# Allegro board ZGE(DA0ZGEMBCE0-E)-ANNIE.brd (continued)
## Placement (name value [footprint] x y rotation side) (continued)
C541  1u/10V_2  [C0201]  138.37 129.56 180 bottom
C542  1u/10V_2  [C0201]  131.2 129.16 0 bottom
C543  1u/10V_2  [C0201]  132.74 128.92 0 bottom
C544  1u/10V_2  [C0201]  129.74 128.87 180 bottom
C545  1u/10V_2  [C0201]  136.03 128.69 180 bottom
C546  1u/10V_2  [C0201]  139.51 128.64 0 bottom
C547  10u/6.3V_4  [C0402_2]  126.89 128.59 180 bottom
C548  1u/10V_2  [C0201]  143.1 128.51 180 bottom
C549  1u/10V_2  [C0201]  131.18 128.44 0 bottom
C550  1u/10V_2  [C0201]  144.62 128.31 180 bottom
C551  1u/10V_2  [C0201]  138.24 128.19 90 bottom
C552  1u/10V_2  [C0201]  129.74 128.11 180 bottom
C553  1u/10V_2  [C0201]  128.42 128.01 0 bottom
C554  10u/6.3V_4  [C0402_2]  132.54 127.94 0 bottom
C555  1u/10V_2  [C0201]  124.94 127.93 270 bottom
C556  1u/10V_2  [C0201]  143.1 127.78 180 bottom
C557  10u/6.3V_4  [C0402_2]  136.24 127.7 180 bottom
C558  10u/6.3V_4  [C0402_2]  139.67 127.62 0 bottom
C559  22u/6.3V_6  [C0603]  109.62 127.55 180 bottom
C560  1u/10V_2  [C0201]  144.62 127.55 180 bottom
C561  1u/10V_2  [C0201]  128.41 127.27 0 bottom
C562  10u/6.3V_4  [C0402_2]  127.04 127.27 180 bottom
C563  1u/10V_2  [C0201]  134.73 127.17 180 bottom
C564  *10u/6.3V_4  [C0402_2]  129.89 127.06 180 bottom
C565  1u/10V_2  [C0201]  143.1 127.04 180 bottom
C566  1u/10V_2  [C0201]  144.62 126.84 180 bottom
C567  10u/6.3V_4  [C0402_2]  132.28 126.57 0 bottom
C568  10u/6.3V_4  [C0402_2]  139.67 126.43 0 bottom
C569  10u/6.3V_4  [C0402_2]  136.11 126.43 180 bottom
C570  1u/10V_2  [C0201]  138.22 126.41 90 bottom
C571  *1u/10V_2  [C0201]  134.69 126.33 180 bottom
C572  *1u/10V_2  [C0201]  144.65 126.1 180 bottom
C573  10u/6.3V_4  [C0402_2]  143.07 126.07 180 bottom
C574  10u/6.3V_4  [C0402_2]  127.32 125.92 180 bottom
C575  1u/6.3V_4  [C0402]  125.27 125.8 180 bottom
C576  *10u/6.3V_4  [C0402_2]  129.89 125.79 180 bottom
C577  *1u/10V_2  [C0201]  134.69 125.56 180 bottom
C578  10u/6.3V_4  [C0402_2]  132.28 125.38 0 bottom
C579  *1u/10V_2  [C0201]  144.65 125.37 180 bottom
C580  10u/6.3V_4  [C0402_2]  139.67 125.16 0 bottom
C581  10u/6.3V_4  [C0402_2]  136.11 125.16 180 bottom
C582  1u/10V_2  [C0201]  124.63 124.91 180 bottom
C583  10u/6.3V_4  [C0402_2]  143.07 124.88 180 bottom
C584  10u/6.3V_4  [C0402_2]  127.35 124.73 180 bottom
C585  *10u/6.3V_4  [C0402_2]  129.89 124.52 180 bottom
C586  10u/6.3V_4  [C0402_2]  132.31 124.19 0 bottom
C587  10u/6.3V_4  [C0402_2]  139.67 123.89 0 bottom
C588  10u/6.3V_4  [C0402_2]  136.11 123.89 180 bottom
C589  1u/10V_2  [C0201]  123.41 123.89 90 bottom
C590  10u/6.3V_4  [C0402_2]  144.01 123.64 180 bottom
C591  10u/6.3V_4  [C0402_2]  127.42 123.53 180 bottom
C592  *10u/6.3V_4  [C0402_2]  129.89 123.25 180 bottom
C593  10u/6.3V_4  [C0402_2]  132.3 123 0 bottom
C594  22u/6.3V_6  [C0603]  124.99 122.98 90 bottom
C595  10u/6.3V_4  [C0402_2]  139.67 122.62 0 bottom
C596  10u/6.3V_4  [C0402_2]  136.11 122.62 180 bottom
C597  10u/6.3V_4  [C0402_2]  144.01 122.44 180 bottom
C598  10u/6.3V_4  [C0402_2]  127.4 122.32 180 bottom
C599  *10u/6.3V_4  [C0402_2]  129.89 121.98 180 bottom
C600  10u/6.3V_4  [C0402_2]  132.3 121.73 0 bottom
C601  0.1u/10V_2  [C0201]  172.36 121.71 0 bottom
C602  22u/6.3V_6  [C0603]  139.67 121.22 0 bottom
C603  22u/6.3V_6  [C0603]  136.11 121.22 180 bottom
C604  22u/6.3V_6  [C0603]  143.55 121.12 180 bottom
C605  10u/6.3V_4  [C0402_2]  127.78 121.1 180 bottom
C606  0.1u/10V_2  [C0201]  172.36 120.95 0 bottom
C607  10u/6.3V_4  [C0402_2]  129.89 120.71 180 bottom
C608  10u/6.3V_4  [C0402_2]  124.57 120.47 0 bottom
C609  10u/6.3V_4  [C0402_2]  132.3 120.46 0 bottom
C610  0.1u/10V_2  [C0201]  172.36 120.18 0 bottom
C611  22u/6.3V_6  [C0603]  127.37 119.75 180 bottom
C612  22u/6.3V_6  [C0603]  143.55 119.7 180 bottom
C613  22u/6.3V_6  [C0603]  139.67 119.7 0 bottom
C614  22u/6.3V_6  [C0603]  136.11 119.7 180 bottom
C615  10u/6.3V_4  [C0402_2]  129.89 119.44 180 bottom
C616  0.1u/10V_2  [C0201]  172.36 119.42 0 bottom
C617  22u/6.3V_6  [C0603]  132.38 119.09 0 bottom
C618  10u/6.3V_4  [C0402_2]  124.48 119.07 0 bottom
C619  0.1u/10V_2  [C0201]  172.36 118.66 0 bottom
C620  22u/6.3V_6  [C0603]  127.37 118.33 180 bottom
C621  22u/6.3V_6  [C0603]  143.55 118.17 180 bottom
C622  22u/6.3V_6  [C0603]  139.67 118.17 0 bottom
C623  22u/6.3V_6  [C0603]  136.11 118.17 180 bottom
C624  *10u/6.3V_4  [C0402_2]  129.89 118.17 180 bottom
C625  *1u/6.3V_4  [C0402]  124.46 117.92 180 bottom
C626  0.1u/10V_2  [C0201]  172.36 117.9 0 bottom
C627  22u/6.3V_6  [C0603]  132.43 117.67 0 bottom
C628  0.1u/10V_2  [C0201]  172.36 117.14 0 bottom
C629  *10u/6.3V_4  [C0402_2]  129.89 116.97 180 bottom
C630  *1u/6.3V_4  [C0402]  124.58 116.88 180 bottom
C631  47u/6.3V_8  [C0805]  127.32 116.57 180 bottom
C632  47u/6.3V_8  [C0805]  143.22 116.4 180 bottom
C633  *47u/6.3V_8  [C0805]  139.54 116.4 0 bottom
C634  *47u/6.3V_8  [C0805]  135.98 116.4 180 bottom
C635  0.1u/10V_2  [C0201]  172.36 116.37 0 bottom
C636  22u/6.3V_6  [C0603]  132.43 116.14 0 bottom
C637  10u/6.3V_4  [C0402_2]  129.9 115.78 180 bottom
C638  10u/6.3V_4  [C0402_2]  124.3 115.76 0 bottom
C639  0.1u/10V_2  [C0201]  172.36 115.61 0 bottom
C640  0.1u/10V_2  [C0201]  172.36 114.85 0 bottom
C641  1u/6.3V_4  [C0402]  124.3 114.62 180 bottom
C642  *10u/6.3V_4  [C0402_2]  129.9 114.57 180 bottom
C643  47u/6.3V_8  [C0805]  127.32 114.54 180 bottom
C644  47u/6.3V_8  [C0805]  143.22 114.36 180 bottom
C645  47u/6.3V_8  [C0805]  139.54 114.36 0 bottom
C646  47u/6.3V_8  [C0805]  135.98 114.36 180 bottom
C647  47u/6.3V_8  [C0805]  132.43 114.36 0 bottom
C648  22u/6.3V_6  [C0603]  155.21 113.86 0 bottom
C649  1u/10V_2  [C0201]  124.08 113.64 270 bottom
C650  100p/50V_4  [C0402]  172.37 113.88 0 bottom
C651  10u/6.3V_4  [C0402_2]  149.75 113.45 270 bottom
C652  *10u/6.3V_4  [C0402_2]  129.92 113.31 180 bottom
C653  1u/10V_2  [C0201]  132.39 112.99 0 bottom
C654  10u/6.3V_4  [C0402_2]  147.54 112.94 270 bottom
C655  0.1u/16V_4  [C0402]  146.37 112.92 270 bottom
C656  1u/10V_2  [C0201]  142 112.84 90 bottom
C657  *0.1u/16V_4  [C0402]  145.41 112.74 270 bottom
C658  10u/6.3V_4  [C0402_2]  137.68 112.73 180 bottom
C659  1u/10V_2  [C0201]  156.1 112.69 180 bottom
C660  0.1u/10V_2  [C0201]  172.36 112.94 0 bottom
C661  *10u/6.3V_4  [C0402_2]  143.27 112.69 180 bottom
C662  22u/6.3V_6  [C0603]  153 112.56 270 bottom
C663  22u/6.3V_6  [C0603]  151.1 112.56 270 bottom
C664  1u/10V_2  [C0201]  135.76 112.56 90 bottom
C665  1u/10V_2  [C0201]  135.04 112.56 90 bottom
C666  10u/6.3V_4  [C0402_2]  133.82 112.56 180 bottom
C667  10u/6.3V_4  [C0402_2]  140.1 112.49 270 bottom
C668  10u/6.3V_4  [C0402_2]  126.19 112.46 180 bottom
C669  22u/6.3V_6  [C0603]  172.74 108.88 0 bottom
C670  22u/6.3V_6  [C0603]  175.41 107.74 180 bottom
C671  0.1u/10V_2  [C0201]  172.36 112.18 0 bottom
C672  47u/6.3V_8  [C0805]  173.04 110.58 0 bottom
C673  0.01u/16V_2  [C0201]  172.36 106.24 0 bottom
C674  1u/6.3V_2  [C0201]  172.23 104.44 270 bottom
C675  0.1u/10V_2  [C0201]  172.81 96.16 180 bottom
C676  10u/6.3V_4  [C0402_2]  181.89 95.43 180 bottom
C677  0.1u/10V_2  [C0201]  172.1 95.27 90 bottom
C678  0.1u/10V_2  [C0201]  182.26 91.48 270 bottom
C679  *1u/6.3V_2  [C0201]  181.5 91.48 270 bottom
C680  0.1u/10V_2  [C0201]  179.72 88.43 90 bottom
C681  0.1u/10V_2  [C0201]  178.96 88.43 90 bottom
C682  0.1u/10V_2  [C0201]  178.2 88.43 90 bottom
C683  0.1u/10V_2  [C0201]  177.44 88.43 90 bottom
C684  0.1u/10V_2  [C0201]  176.68 88.43 90 bottom
C685  0.1u/10V_2  [C0201]  175.91 88.43 90 bottom
C686  0.1u/10V_2  [C0201]  175.15 88.43 90 bottom
C687  0.1u/10V_2  [C0201]  174.39 88.43 90 bottom
C688  0.1u/10V_2  [C0201]  173.63 88.43 270 bottom
C689  10u/6.3V_6  [C0603]  96.54 70.54 0 bottom
C690  10u/6.3V_6  [C0603]  96.57 69.09 0 bottom
C691  10u/6.3V_6  [C0603]  96.59 72.57 270 bottom
C692  2.2u/10V_4  [C0402]  91.38 64.06 180 bottom
C693  0.1u/16V_4  [C0402]  91.94 65.05 180 bottom
C694  0.022u/25V_4  [C0402]  177.69 62.33 180 bottom
C695  10u/6.3V_6  [C0603]  95.94 64.04 0 bottom
C696  *220p/50V_4  [C0402]  12.21 51.63 180 bottom
C697  *220p/50V_4  [C0402]  9.29 51.63 0 bottom
C698  0.1u/16V_4  [C0402]  5.84 63.16 180 bottom
C699  1u/6.3V_4  [C0402]  95.65 62.84 0 bottom
C700  1u/6.3V_4  [C0402]  97.06 59.83 90 bottom
C701  220p/50V_4  [C0402]  195.94 59.63 90 bottom
C702  *2.2u/10V_4  [C0402]  178.88 58.7 270 bottom
C703  47u/6.3V_6  [C0603]  272.56 58.33 180 bottom
C704  47u/6.3V_6  [C0603]  270.26 57.79 90 bottom
C705  0.1u/16V_4  [C0402]  180.32 59.14 0 bottom
C706  0.1u/16V_4  [C0402]  178.48 56.95 180 bottom
C707  220p/50V_4  [C0402]  197.12 56.81 90 bottom
C708  1u/6.3V_2  [C0201]  270.6 55.97 270 bottom
C709  0.1u/16V_4  [C0402]  178.47 53.58 0 bottom
C710  10u/6.3V_4  [C0402_2]  268.04 55.74 90 bottom
C711  0.1u/16V_4  [C0402]  206.27 55.29 180 bottom
C712  *2.2u/10V_4  [C0402]  178.49 52.62 0 bottom
C713  1u/6.3V_2  [C0201]  264.05 54.05 270 bottom
C714  1u/6.3V_2  [C0201]  263.26 54.05 270 bottom
C715  10u/6.3V_4  [C0402_2]  270.99 53.89 270 bottom
C716  10u/6.3V_4  [C0402_2]  269.79 53.89 270 bottom
C717  10u/6.3V_4  [C0402_2]  272.18 53.86 270 bottom
C718  1u/6.3V_2  [C0201]  260.72 53.79 0 bottom
C719  1u/6.3V_2  [C0201]  262.53 53.41 270 bottom
C720  1u/6.3V_2  [C0201]  266.54 53.4 270 bottom
C721  1u/6.3V_2  [C0201]  261.74 53.38 270 bottom
C722  1u/6.3V_2  [C0201]  260.01 52.87 270 bottom
C723  1u/6.3V_2  [C0201]  260.75 52.85 270 bottom
C724  1u/6.3V_2  [C0201]  264.77 52.7 270 bottom
C725  1u/6.3V_2  [C0201]  264.06 52.7 270 bottom
C726  1u/6.3V_2  [C0201]  265.97 52.54 180 bottom
C727  1u/6.3V_2  [C0201]  263.09 52.19 0 bottom
C728  1u/6.3V_2  [C0201]  262.1 52.19 180 bottom
C729  0.1u/16V_4  [C0402]  178.48 49.66 0 bottom
C730  10u/6.3V_4  [C0402_2]  268.34 51.63 0 bottom
C731  0.1u/10V_2  [C0201]  257.98 51.48 180 bottom
C732  1u/6.3V_2  [C0201]  262.1 51.43 180 bottom
C733  1u/6.3V_2  [C0201]  266.52 51.35 180 bottom
C734  0.22u/10V_4  [C0402]  184.3 51.1 0 bottom
C735  1u/6.3V_2  [C0201]  260.8 50.75 90 bottom
C736  1u/6.3V_2  [C0201]  260.09 50.75 90 bottom
C737  0.1u/10V_2  [C0201]  257.98 50.71 180 bottom
C738  1u/6.3V_2  [C0201]  265.31 50.54 0 bottom
C739  1u/6.3V_2  [C0201]  262.09 50.49 180 bottom
C740  1u/6.3V_2  [C0201]  267.29 50.14 180 bottom
C741  0.22u/10V_4  [C0402]  184.3 50.08 0 bottom
C742  1u/6.3V_2  [C0201]  264.05 49.86 180 bottom
C743  1u/6.3V_2  [C0201]  265.29 49.82 0 bottom
C744  *22u/25V_8  [C0805]  284.5 49.7 270 bottom
C745  1u/6.3V_2  [C0201]  260.73 49.63 0 bottom
C746  1u/6.3V_2  [C0201]  262.05 49.62 270 bottom
C747  1u/6.3V_4  [C0402]  100.27 49.24 0 bottom
C748  0.22u/6.3V_2  [C0201]  270.64 49.21 180 bottom
C749  1u/6.3V_2  [C0201]  265.3 49.05 0 bottom
C750  1u/6.3V_2  [C0201]  264.03 48.94 270 bottom
C751  0.1u/10V_2  [C0201]  258.24 48.94 180 bottom
C752  1u/6.3V_2  [C0201]  260.53 48.91 0 bottom
C753  1u/6.3V_2  [C0201]  263.04 48.86 180 bottom
C754  1u/6.3V_2  [C0201]  266.54 48.78 270 bottom
C755  0.22u/6.3V_2  [C0201]  270.64 48.49 180 bottom
C756  10u/6.3V_4  [C0402_2]  267.86 48.33 270 bottom
C757  1000p/50V_4  [C0402]  18.47 48.2 180 bottom
C758  0.1u/10V_2  [C0201]  258.24 48.17 180 bottom
C759  10u/6.3V_6  [C0603]  175.33 47.5 0 bottom
C760  0.22u/10V_4  [C0402]  184.3 48.05 0 bottom
C761  *1u/6.3V_4  [C0402]  98.39 48.33 0 bottom
C762  1u/6.3V_2  [C0201]  263.96 47.57 180 bottom
C763  1u/6.3V_2  [C0201]  263.07 47.57 90 bottom
C764  1u/6.3V_2  [C0201]  262.36 47.56 90 bottom
C765  10u/6.3V_6  [C0603]  102.03 47.44 180 bottom
C766  10u/6.3V_6  [C0603]  99.99 47.39 90 bottom
C767  10u/6.3V_4  [C0402_2]  16.17 47.09 270 bottom
C768  0.1u/16V_4  [C0402]  15.05 47.09 270 bottom
C769  0.22u/10V_4  [C0402]  184.3 47.03 0 bottom
C770  1u/6.3V_4  [C0402]  98.39 47.31 0 bottom
C771  15p/25V_2  [C0201]  201.95 46.92 270 bottom
C772  0.047u/16V_4  [C0402]  285.54 46.63 90 bottom
C773  0.047u/16V_4  [C0402]  284.57 46.63 90 bottom
C774  0.047u/16V_4  [C0402]  286.51 46.62 90 bottom
C775  0.047u/16V_4  [C0402]  283.61 46.62 90 bottom
C776  10u/6.3V_4  [C0402_2]  15.94 45.33 90 bottom
C777  0.1u/16V_4  [C0402]  14.85 45.33 90 bottom
C778  15p/25V_2  [C0201]  201.95 45.17 90 bottom
C779  0.22u/10V_4  [C0402]  184.3 45 0 bottom
C780  0.22u/10V_4  [C0402]  184.3 43.98 0 bottom
C781  0.1u/10V_2  [C0201]  253.51 43.6 180 bottom
C782  1u/6.3V_2  [C0201]  241.95 42.46 90 bottom
C783  0.22u/10V_4  [C0402]  184.3 41.95 0 bottom
C784  0.22u/10V_4  [C0402]  184.3 40.94 0 bottom
C785  *1u/6.3V_4  [C0402]  98.55 40.76 270 bottom
C786  22u/6.3V_6  [C0603]  202.61 40.16 180 bottom
C787  1u/6.3V_4  [C0402]  212.31 39.15 90 bottom
C788  *22u/25V_8  [C0805]  284.93 38.65 0 bottom
C789  1u/6.3V_4  [C0402]  218.69 38.57 270 bottom
C790  4.7u/6.3V_4  [C0402_2]  217.47 38.56 270 bottom
C791  1u/6.3V_4  [C0402]  216.38 38.56 270 bottom
C792  0.1u/10V_2  [C0201]  246.65 38.52 180 bottom
C793  22u/6.3V_6  [C0603]  210.26 38.16 180 bottom
C794  0.1u/16V_4  [C0402]  289.78 38.01 90 bottom
C795  0.1u/16V_4  [C0402]  288.82 38.01 90 bottom
C796  0.1u/16V_4  [C0402]  290.76 38.01 90 bottom
C797  1u/6.3V_4  [C0402]  220.16 37.98 90 bottom
C798  0.1u/16V_4  [C0402]  213.79 37.96 180 bottom
C799  0.1u/10V_2  [C0201]  235.39 37.91 0 bottom
C800  1000p/50V_4  [C0402]  201.8 37.97 180 bottom
C801  0.1u/10V_2  [C0201]  221.66 37.47 180 bottom
C802  2.2u/10V_4  [C0402]  215.18 37.26 90 bottom
C803  220p/25V_2  [C0201]  252.47 37 0 bottom
C804  1u/6.3V_4  [C0402]  277.39 36.87 270 bottom
C805  1000p/50V_4  [C0402]  276.37 36.87 270 bottom
C806  22u/6.3V_6  [C0603]  266.08 36.74 270 bottom
C807  220p/25V_2  [C0201]  252.44 35.88 0 bottom
C808  22u/6.3V_6  [C0603]  215.99 35.66 0 bottom
C809  22u/6.3V_6  [C0603]  268.62 35.65 0 bottom
C810  4.7u/6.3V_4  [C0402_2]  218.19 35.61 0 bottom
C811  0.1u/16V_4  [C0402]  220.47 35.16 0 bottom
C812  0.1u/16V_4  [C0402]  264.2 35.14 270 bottom
C813  1u/6.3V_4  [C0402]  211.15 33.97 180 bottom
C814  0.1u/16V_4  [C0402]  221.23 33.8 0 bottom
C815  0.1u/10V_2  [C0201]  47.9 33.47 180 bottom
C816  0.1u/10V_2  [C0201]  227.33 33.44 0 bottom
C817  1u/6.3V_4  [C0402]  213.36 33.18 90 bottom
C818  4.7u/6.3V_4  [C0402_2]  219.73 32.93 270 bottom
C819  10u/6.3V_4  [C0402_2]  218.53 32.93 270 bottom
C820  0.1u/16V_4  [C0402]  217.44 32.93 270 bottom
C821  10u/6.3V_4  [C0402_2]  216.35 32.93 270 bottom
C822  0.1u/10V_2  [C0201]  47.9 32.71 0 bottom
C823  0.1u/16V_4  [C0402]  265.19 32.43 0 bottom
C824  0.1u/10V_2  [C0201]  47.9 31.92 0 bottom
C825  0.1u/10V_2  [C0201]  227 31.76 270 bottom
C826  1u/6.3V_4  [C0402]  213.44 31.46 90 bottom
C827  1u/6.3V_4  [C0402]  263.92 31.03 90 bottom
C828  1000p/50V_4  [C0402]  262.91 31.03 90 bottom
C829  100p/50V_4  [C0402]  261.89 31.03 270 bottom
C830  *0.1u/10V_2  [C0201]  89.27 30.94 0 bottom
C831  1000p/50V_4  [C0402]  266.72 30.9 270 bottom
C832  0.1u/16V_4  [C0402]  216.05 30.69 90 bottom
C833  0.1u/16V_4  [C0402]  220.09 30.59 270 bottom
C834  0.22u/10V_4  [C0402]  257.7 30.52 270 bottom
C835  0.22u/10V_4  [C0402]  256.47 30.52 270 bottom
C836  0.1u/16V_4  [C0402]  222.9 30.52 180 bottom
C837  10u/6.3V_6  [C0603]  97.28 31.06 270 bottom
C838  0.1u/16V_4  [C0402]  209.61 30.06 180 bottom
C839  1u/6.3V_4  [C0402]  268.88 29.51 270 bottom
C840  1000p/50V_4  [C0402]  267.86 29.51 270 bottom
C841  0.01u/16V_2  [C0201]  60.09 29.38 0 bottom
C842  0.1u/10V_2  [C0201]  58.82 29.38 270 bottom
C843  0.01u/16V_2  [C0201]  57.8 29.38 90 bottom
C844  1u/6.3V_4  [C0402]  96.13 29.26 0 bottom
C845  1u/6.3V_4  [C0402]  214.78 29.27 270 bottom
C846  0.1u/16V_4  [C0402]  213.53 29.25 270 bottom
C847  0.1u/10V_2  [C0201]  56.28 27.98 0 bottom
C848  1u/6.3V_4  [C0402]  98.47 28.87 90 bottom
C849  1u/6.3V_4  [C0402]  97.5 28.88 90 bottom
C850  1000p/50V_4  [C0402]  33.78 28.85 0 bottom
C851  *0.1u/10V_2  [C0201]  208.18 28.46 270 bottom
C852  4.7u/6.3V_4  [C0402_2]  211.04 28.41 0 bottom
C853  4.7u/6.3V_2  [C0201]  59.84 24.55 0 bottom
C854  *0.1u/16V_4  [C0402]  252.88 28.11 90 bottom
C855  0.01u/16V_2  [C0201]  56.28 28.87 180 bottom
C856  0.22u/10V_4  [C0402]  263.85 27.83 90 bottom
C857  0.22u/10V_4  [C0402]  262.88 27.83 90 bottom
C858  0.1u/16V_4  [C0402]  43.73 27.63 180 bottom
C859  1u/6.3V_2  [C0201]  62.19 27.57 270 bottom
C860  0.1u/10V_2  [C0201]  59.84 27.6 180 bottom
C861  0.1u/10V_2  [C0201]  56.28 26.97 0 bottom
C862  0.22u/10V_4  [C0402]  182.95 26.81 0 bottom
C863  1u/6.3V_4  [C0402]  23.51 26.46 270 bottom
C864  1u/6.3V_4  [C0402]  22.5 26.46 270 bottom
C865  0.01u/16V_2  [C0201]  59.86 26.81 0 bottom
C866  *10p/50V_4  [C0402]  62.65 26.16 180 bottom
C867  0.1u/16V_4  [C0402]  209.47 26.14 0 bottom
C868  0.01u/16V_2  [C0201]  56.28 26.2 180 bottom
C869  0.22u/10V_4  [C0402]  182.95 25.85 0 bottom
C870  0.1u/10V_2  [C0201]  208.61 25.3 180 bottom
C871  0.1u/10V_2  [C0201]  59.84 25.31 180 bottom
C872  0.1u/10V_2  [C0201]  56.28 25.31 0 bottom
C873  *1000p/50V_4  [C0402]  93.07 26.37 270 bottom
C874  1000p/50V_4  [C0402]  263.67 24.48 180 bottom
C875  0.01u/16V_2  [C0201]  59.84 26.03 0 bottom
C876  0.22u/10V_4  [C0402]  182.52 24.12 0 bottom
C877  0.1u/16V_4  [C0402]  70.43 23.97 180 bottom
C878  0.01u/16V_2  [C0201]  56.28 24.43 180 bottom
C879  10u/6.3V_4  [C0402_2]  33.55 23.79 90 bottom
C880  0.1u/16V_4  [C0402]  32.4 23.79 90 bottom
C881  *0.1u/10V_2  [C0201]  229.57 23.72 90 bottom
C882  22u/6.3V_6  [C0603]  273.2 23.66 0 bottom
C883  HDD@0.01u/50V_4  [C0402]  49.89 23.31 180 bottom
C884  0.1u/10V_2  [C0201]  59.96 28.36 180 bottom
C885  0.22u/10V_4  [C0402]  182.52 23.16 0 bottom
C886  22u/6.3V_6  [C0603]  270.15 23.03 180 bottom
C887  4.7u/6.3V_4  [C0402_2]  206.44 22.9 0 bottom
C888  0.1u/10V_2  [C0201]  55.77 22.52 0 bottom
C889  HDD@0.01u/50V_4  [C0402]  41.04 22.39 180 bottom
C890  0.1u/10V_2  [C0201]  77.71 22.34 180 bottom
C891  HDD@0.01u/50V_4  [C0402]  49.9 22.34 180 bottom
C892  0.01u/16V_2  [C0201]  59.96 23.41 0 bottom
C893  0.01u/16V_2  [C0201]  59.15 22.24 270 bottom
C894  0.1u/10V_2  [C0201]  58.31 22.27 90 bottom
C895  0.1u/16V_4  [C0402]  79.57 22.22 180 bottom
C896  0.22u/25V_6  [C0603]  71.6 21.89 270 bottom
C897  0.01u/16V_2  [C0201]  56.28 23.66 180 bottom
C898  10u/6.3V_4  [C0402_2]  76.32 22.01 180 bottom
C899  0.22u/10V_4  [C0402]  182.82 21.76 0 bottom
C900  0.1u/16V_4  [C0402]  267.05 21.45 270 bottom
C901  0.1u/16V_4  [C0402]  72.84 21.44 270 bottom
C902  HDD@0.01u/50V_4  [C0402]  41.04 21.38 180 bottom
C903  HDD@0.01u/50V_4  [C0402]  50.01 21.02 180 bottom
C904  0.22u/10V_4  [C0402]  182.82 20.74 0 bottom
C905  *10u/6.3V_4  [C0402_2]  79.14 20.74 180 bottom
C906  0.1u/16V_4  [C0402]  75.3 20.72 0 bottom
C907  0.1u/10V_2  [C0201]  87.88 20.51 0 bottom
C908  HDD@0.01u/50V_4  [C0402]  41.04 20.36 180 bottom
C909  0.1u/10V_2  [C0201]  90.77 20.23 180 bottom
C910  HDD@0.01u/50V_4  [C0402]  50.01 20.06 180 bottom
C911  1u/6.3V_4  [C0402]  266.97 19.47 180 bottom
C912  *0.1u/16V_4  [C0402]  252.49 19.47 270 bottom
C913  0.22u/10V_4  [C0402]  180.71 20.03 0 bottom
C914  HDD@0.01u/50V_4  [C0402]  41.04 19.35 180 bottom
C915  TPM@0.1u/16V_4  [C0402]  242.74 19.22 270 bottom
C916  TPM@0.1u/16V_4  [C0402]  241.52 19.17 270 bottom
C917  1u/6.3V_2  [C0201]  278.4 19.09 0 bottom
C918  18p/50V_4  [C0402]  228.19 18.93 180 bottom
C919  0.1u/16V_4  [C0402]  259.99 18.58 180 bottom
C920  0.22u/10V_4  [C0402]  180.71 19.02 0 bottom
C921  0.1u/16V_4  [C0402]  48.22 18.32 0 bottom
C922  18p/50V_4  [C0402]  225.19 16.87 90 bottom
C923  1000p/50V_4  [C0402]  264.81 15.41 90 bottom
C924  1u/6.3V_4  [C0402]  263.8 15.41 90 bottom
C925  0.01u/50V_4  [C0402]  262.71 15.41 270 bottom
C926  1000p/50V_4  [C0402]  261.66 15.41 90 bottom
C927  0.1u/16V_4  [C0402]  225.55 14.52 90 bottom
C928  0.1u/16V_4  [C0402]  248.28 14.37 180 bottom
C929  1u/6.3V_2  [C0201]  271.93 14.07 180 bottom
C930  0.1u/10V_2  [C0201]  280.18 12.18 0 bottom
C931  0.1u/16V_4  [C0402]  251.35 12.43 0 bottom
C932  0.1u/10V_2  [C0201]  274.72 12.39 0 bottom
C933  0.01u/16V_2  [C0201]  275.89 13.63 270 bottom
C934  1u/6.3V_2  [C0201]  272.54 11.5 270 bottom
C935  0.1u/16V_4  [C0402]  233.7 11.47 180 bottom
C936  0.1u/10V_2  [C0201]  280.18 11.19 0 bottom
C937  4.7u/6.3V_2  [C0201]  274.77 11.5 90 bottom
C938  0.01u/16V_2  [C0201]  280.18 13.15 0 bottom
C939  TPM@0.1u/16V_4  [C0402]  239.29 10.33 90 bottom
C940  TPM@0.1u/16V_4  [C0402]  238.27 10.33 90 bottom
C941  TPM@10u/6.3V_6  [C0603]  235.98 10.15 0 bottom
C942  0.01u/16V_2  [C0201]  280.56 9.54 0 top
C943  22u/6.3V_6  [C0603]  172.74 107.36 0 bottom
C945  *1000p/50V_4  [C0402]  98.11 17.57 180 bottom
CG1  10u/6.3V_6  [C0603]  8.53 141.62 0 top
CG2  10u/6.3V_6  [C0603]  35.45 160.76 180 top
CG3  10u/6.3V_6  [C0603]  43.52 163.56 180 top
CG4  10u/6.3V_6  [C0603]  45.03 162.04 0 top
CG5  22u/6.3V_6  [C0603]  11.12 137.25 180 top
CG6  0.47u/6.3V_2  [C0201]  12.97 137.18 180 top
CG7  0.47u/6.3V_2  [C0201]  7.82 131.26 270 top
CG8  22u/6.3V_6  [C0603]  102.7 129.58 180 top
CG9  0.47u/6.3V_2  [C0201]  7.81 128.62 90 top
CG10  10u/6.3V_6  [C0603]  102.7 128.06 180 top
CG11  10u/6.3V_6  [C0603]  102.7 126.53 180 top
CG12  10u/6.3V_6  [C0603]  102.7 125.01 180 top
CG13  0.47u/6.3V_2  [C0201]  7.83 124.2 90 top
CG14  0.47u/6.3V_2  [C0201]  101.93 123.86 0 top
CG15  0.47u/6.3V_2  [C0201]  101.93 123.1 0 top
CG16  4.7u/6.3V_6  [C0603]  102.7 121.96 180 top
CG17  0.47u/6.3V_2  [C0201]  7.89 121.33 90 top
CG18  0.47u/6.3V_2  [C0201]  101.93 120.82 0 top
CG19  0.47u/6.3V_2  [C0201]  101.93 120.05 0 top
CG20  0.47u/6.3V_2  [C0201]  7.87 119.62 270 top
CG21  10u/6.3V_6  [C0603]  102.7 118.91 180 top
CG22  10u/6.3V_6  [C0603]  102.7 117.39 180 top
CG23  10u/6.3V_6  [C0603]  102.7 115.76 180 top
CG24  0.47u/6.3V_2  [C0201]  7.79 114.56 90 top
CG25  22u/6.3V_6  [C0603]  102.7 114.34 180 top
CG26  0.47u/6.3V_2  [C0201]  7.81 113.1 90 top
CG27  10u/6.3V_6  [C0603]  102.76 112.82 180 top
CG28  10u/6.3V_6  [C0603]  102.76 111.29 180 top
CG29  22u/6.3V_6  [C0603]  29.45 108.19 180 top
CG30  4.7u/6.3V_6  [C0603]  102.79 107.53 180 top
CG31  4.7u/6.3V_6  [C0603]  29.48 106.77 180 top
CG32  0.47u/6.3V_2  [C0201]  13.9 105.52 180 top
CG33  0.47u/6.3V_2  [C0201]  10.38 105.51 0 top
CG34  0.47u/6.3V_2  [C0201]  12.14 105.51 0 top
CG35  4.7u/6.3V_6  [C0603]  29.36 105.14 180 top
CG36  4.7u/6.3V_6  [C0603]  24.66 104.69 90 top
CG37  10u/6.3V_6  [C0603]  26.18 104.69 90 top
CG38  *220p/25V_2  [C0201]  16.66 104.3 270 top
CG39  4.7u/6.3V_6  [C0603]  23.97 101.01 270 top
CG40  22u/6.3V_6  [C0603]  25.39 101.01 90 top
CG41  10u/6.3V_6  [C0603]  26.82 101.01 270 top
CG42  10u/6.3V_6  [C0603]  28.34 101.01 270 top
CG43  22u/6.3V_6  [C0603]  102.75 100.91 180 top
CG44  22u/6.3V_6  [C0603]  102.75 99.43 180 top
CG45  *220p/25V_2  [C0201]  27.19 99.05 180 top
CG46  4.7u/6.3V_6  [C0603]  76.47 98.59 270 top
CG47  4.7u/6.3V_6  [C0603]  78 98.59 270 top
CG48  4.7u/6.3V_6  [C0603]  79.52 98.59 90 top
CG49  22u/6.3V_6  [C0603]  81.04 98.59 90 top
CG50  10u/6.3V_6  [C0603]  82.57 97.58 90 top
CG51  4.7u/6.3V_6  [C0603]  84.09 96.43 270 top
CG52  4.7u/6.3V_6  [C0603]  85.62 96.43 90 top
CG53  4.7u/6.3V_6  [C0603]  87.14 96.43 90 top
CG54  10u/6.3V_6  [C0603]  88.66 96.43 90 top
CG55  0.47u/6.3V_2  [C0201]  76.73 93.13 270 top
CG56  0.47u/6.3V_2  [C0201]  77.49 93.13 270 top
CG57  0.47u/6.3V_2  [C0201]  78.25 93.13 270 top
CG58  0.47u/6.3V_2  [C0201]  79.14 93.13 270 top
CG59  0.47u/6.3V_2  [C0201]  79.9 93.13 270 top
CG60  22u/6.3V_6  [C0603]  81.04 93.03 90 top
CG61  10u/6.3V_6  [C0603]  82.57 93.03 270 top
CG62  22u/6.3V_6  [C0603]  84.09 93.03 90 top
CG63  4.7u/6.3V_6  [C0603]  85.62 93.03 90 top
CG64  10u/6.3V_6  [C0603]  87.14 93.03 270 top
CG65  4.7u/6.3V_6  [C0603]  88.66 93.03 270 top
CG66  *220p/25V_2  [C0201]  16.73 94.25 90 top
CG67  *220p/25V_2  [C0201]  23.54 92.27 90 top
CG68  18p/50V_4  [C0402]  37.86 87.8 180 top
CG69  0.1u/16V_4  [C0402]  40.07 86.75 90 top
CG70  0.1u/16V_4  [C0402]  41.09 86.75 90 top
CG71  0.1u/16V_4  [C0402]  42.06 86.66 90 top
CG72  0.1u/16V_4  [C0402]  43.07 86.66 90 top
CG73  0.1u/16V_4  [C0402]  44.09 86.66 90 top
CG74  0.1u/16V_4  [C0402]  45.1 86.66 90 top
CG75  0.1u/16V_4  [C0402]  47.14 86.66 90 top
CG76  0.1u/16V_4  [C0402]  46.17 86.62 90 top
CG77  10p/25V_2  [C0201]  33.8 86.53 270 top
CG78  0.1u/16V_4  [C0402]  37.36 86.27 90 top
CG79  0.1u/16V_4  [C0402]  38.37 86.27 90 top
CG80  10p/25V_2  [C0201]  32.91 85.13 270 top
CG81  0.01u/50V_4  [C0402]  33.17 83.73 270 top
CG82  820p/50V_4  [C0402]  27.39 80.5 0 top
CG83  *0.1u/16V_4  [C0402]  34.39 79.81 90 top
CG84  0.1u/16V_4  [C0402]  46.22 79.39 90 top
CG85  10u/6.3V_6  [C0603]  32.48 157.14 270 bottom
CG86  10u/6.3V_6  [C0603]  42.54 157.45 180 bottom
CG87  22u/6.3V_6  [C0603]  38.93 157.01 180 bottom
CG88  22u/6.3V_6  [C0603]  59.37 157.18 180 bottom
CG89  0.47u/6.3V_2  [C0201]  37.23 156.61 90 bottom
CG90  0.47u/6.3V_2  [C0201]  61.66 157.09 180 bottom
CG91  22u/6.3V_6  [C0603]  30.44 156.84 0 bottom
CG92  10u/6.3V_6  [C0603]  35.53 156.35 0 bottom
CG93  10u/6.3V_6  [C0603]  65.72 156.78 90 bottom
CG94  22u/6.3V_6  [C0603]  72.43 156.63 180 bottom
CG95  0.47u/6.3V_2  [C0201]  63.08 156.56 0 bottom
CG96  0.47u/6.3V_2  [C0201]  74.11 156.48 270 bottom
CG97  0.47u/6.3V_2  [C0201]  81.54 156.11 270 bottom
CG98  0.47u/6.3V_2  [C0201]  33.8 156.2 90 bottom
CG99  0.47u/6.3V_2  [C0201]  82.27 156.1 270 bottom
CG100  0.47u/6.3V_2  [C0201]  64.46 156.1 0 bottom
CG101  0.47u/6.3V_2  [C0201]  80.8 156.09 270 bottom
CG102  22u/6.3V_6  [C0603]  26.55 156.08 0 bottom
CG103  0.47u/6.3V_2  [C0201]  42.31 156.07 0 bottom
CG104  0.47u/6.3V_2  [C0201]  79.67 155.97 0 bottom
CG105  0.47u/6.3V_2  [C0201]  58.72 155.97 270 bottom
CG106  0.47u/6.3V_2  [C0201]  57.93 155.97 270 bottom
CG107  0.47u/6.3V_2  [C0201]  67.29 155.94 180 bottom
CG108  0.47u/6.3V_2  [C0201]  52.01 155.92 180 bottom
CG109  0.47u/6.3V_2  [C0201]  49.09 155.9 0 bottom
CG110  0.47u/6.3V_2  [C0201]  60.62 155.87 180 bottom
CG111  0.47u/6.3V_2  [C0201]  76.52 155.85 180 bottom
CG112  0.47u/6.3V_2  [C0201]  30.31 155.77 0 bottom
CG113  0.47u/6.3V_2  [C0201]  45.36 155.82 180 bottom
CG114  0.47u/6.3V_2  [C0201]  52.98 155.67 90 bottom
CG115  10u/6.3V_6  [C0603]  70.31 155.6 90 bottom
CG116  22u/6.3V_6  [C0603]  68.85 155.6 90 bottom
CG117  0.47u/6.3V_2  [C0201]  37.64 155.52 90 bottom
CG118  10u/6.3V_6  [C0603]  39.52 155.44 180 bottom
CG119  0.47u/6.3V_2  [C0201]  32.51 155.34 90 bottom
CG120  0.47u/6.3V_2  [C0201]  31.73 155.32 90 bottom
CG121  0.47u/6.3V_2  [C0201]  41.32 155.29 270 bottom
CG122  22u/6.3V_6  [C0603]  83.99 155.21 90 bottom
CG123  0.47u/6.3V_2  [C0201]  74.91 155.13 180 bottom
CG124  0.47u/6.3V_2  [C0201]  55.27 154.86 180 bottom
CG125  0.47u/6.3V_2  [C0201]  61.64 154.86 90 bottom
CG126  0.47u/6.3V_2  [C0201]  56.48 154.85 0 bottom
CG127  0.47u/6.3V_2  [C0201]  71.82 154.78 270 bottom
CG128  0.47u/6.3V_2  [C0201]  54.21 154.78 180 bottom
CG129  0.47u/6.3V_2  [C0201]  53.08 154.63 270 bottom
CG130  0.47u/6.3V_2  [C0201]  31.22 154.25 180 bottom
CG131  0.47u/6.3V_2  [C0201]  37.71 154.25 90 bottom
CG132  0.47u/6.3V_2  [C0201]  32.51 154.25 270 bottom
CG133  0.47u/6.3V_2  [C0201]  38.7 154.21 90 bottom
CG134  0.47u/6.3V_2  [C0201]  63.24 154.18 270 bottom
CG135  0.47u/6.3V_2  [C0201]  48 154.14 270 bottom
CG136  0.47u/6.3V_2  [C0201]  56.43 154.09 0 bottom
CG137  0.47u/6.3V_2  [C0201]  78.63 154.02 270 bottom
CG138  0.47u/6.3V_2  [C0201]  25.91 153.83 90 bottom
CG139  10u/6.3V_6  [C0603]  46.88 153.71 90 bottom
CG140  0.47u/6.3V_2  [C0201]  68.29 153.69 270 bottom
CG141  0.47u/6.3V_2  [C0201]  61.56 153.57 90 bottom
CG142  0.47u/6.3V_2  [C0201]  76.08 153.43 270 bottom
CG143  22u/6.3V_6  [C0603]  40.2 153.38 90 bottom
CG144  0.47u/6.3V_2  [C0201]  45.43 153.34 270 bottom
CG145  0.47u/6.3V_2  [C0201]  71.89 153.27 270 bottom
CG146  0.47u/6.3V_2  [C0201]  31.22 153.26 180 bottom
CG147  0.47u/6.3V_2  [C0201]  53.08 153.25 270 bottom
CG148  0.47u/6.3V_2  [C0201]  83.6 153.24 270 bottom
CG149  0.47u/6.3V_2  [C0201]  33.19 153.23 90 bottom
CG150  22u/6.3V_6  [C0603]  54.55 152.95 90 bottom
CG151  10u/6.3V_6  [C0603]  70.03 152.88 0 bottom
CG152  0.47u/6.3V_2  [C0201]  37.66 152.85 90 bottom
CG153  0.47u/6.3V_2  [C0201]  25.89 152.82 90 bottom
CG154  0.47u/6.3V_2  [C0201]  68.34 152.65 90 bottom
CG155  0.47u/6.3V_2  [C0201]  47.97 152.37 90 bottom
CG156  22u/6.3V_6  [C0603]  38.78 152.37 90 bottom
CG157  22u/6.3V_6  [C0603]  56.08 152.34 270 bottom
CG158  0.47u/6.3V_2  [C0201]  79.33 152.08 0 bottom
CG159  0.47u/6.3V_2  [C0201]  25.76 151.91 0 bottom
CG160  0.47u/6.3V_2  [C0201]  71.91 151.9 270 bottom
CG161  22u/6.3V_6  [C0603]  63.04 151.81 270 bottom
CG162  10u/6.3V_6  [C0603]  77.31 151.81 90 bottom
CG163  0.47u/6.3V_2  [C0201]  83.73 151.76 270 bottom
CG164  0.47u/6.3V_2  [C0201]  53 151.73 270 bottom
CG165  0.47u/6.3V_2  [C0201]  30.09 151.73 90 bottom
CG166  0.47u/6.3V_2  [C0201]  41.27 151.68 270 bottom
CG167  0.47u/6.3V_2  [C0201]  57.21 151.52 270 bottom
CG168  10u/6.3V_6  [C0603]  69.11 151.42 0 bottom
CG169  *47u/6.3V_8  [C0805]  86.13 151.19 180 bottom
CG170  0.47u/6.3V_2  [C0201]  25.76 151.13 0 bottom
CG171  0.47u/6.3V_2  [C0201]  79.18 150.98 180 bottom
CG172  0.47u/6.3V_2  [C0201]  44.88 150.95 180 bottom
CG173  0.47u/6.3V_2  [C0201]  29.57 150.83 180 bottom
CG174  0.47u/6.3V_2  [C0201]  41.07 150.82 0 bottom
CG175  0.47u/6.3V_2  [C0201]  64.74 150.8 270 bottom
CG176  0.47u/6.3V_2  [C0201]  34.08 150.79 270 bottom
CG177  10u/6.3V_6  [C0603]  60.95 150.74 0 bottom
CG178  0.47u/6.3V_2  [C0201]  37.76 150.56 90 bottom
CG179  22u/6.3V_6  [C0603]  54.5 150.31 0 bottom
CG180  0.47u/6.3V_2  [C0201]  49.37 150.11 270 bottom
CG181  0.47u/6.3V_2  [C0201]  80.17 150.01 270 bottom
CG182  0.47u/6.3V_2  [C0201]  45.64 149.95 180 bottom
CG183  0.47u/6.3V_2  [C0201]  56.56 149.88 270 bottom
CG184  0.47u/6.3V_2  [C0201]  79.1 149.86 180 bottom
CG185  0.47u/6.3V_2  [C0201]  48.58 149.76 270 bottom
CG186  0.47u/6.3V_2  [C0201]  85.01 149.54 270 bottom
CG187  10u/6.3V_6  [C0603]  86.97 149.5 180 bottom
CG188  0.47u/6.3V_2  [C0201]  82.74 149.39 270 bottom
CG189  0.47u/6.3V_2  [C0201]  30.21 149.09 90 bottom
CG190  0.47u/6.3V_2  [C0201]  60.78 149.02 90 bottom
CG191  *820p/50V_4  [C0402]  53.73 148.75 180 bottom
CG192  *820p/50V_4  [C0402]  56.07 148.37 0 bottom
CG193  0.47u/6.3V_2  [C0201]  69.82 148.15 180 bottom
CG194  22u/6.3V_6  [C0603]  86.96 148.05 180 bottom
CG195  0.47u/6.3V_2  [C0201]  43.33 148 0 bottom
CG196  0.47u/6.3V_2  [C0201]  30.17 147.97 270 bottom
CG197  0.47u/6.3V_2  [C0201]  60.93 147.95 180 bottom
CG198  0.47u/6.3V_2  [C0201]  73.87 147.84 0 bottom
CG199  0.47u/6.3V_2  [C0201]  31.25 147.71 180 bottom
CG200  0.47u/6.3V_2  [C0201]  75.56 147.62 0 bottom
CG201  0.47u/6.3V_2  [C0201]  72.49 147.29 180 bottom
CG202  0.47u/6.3V_2  [C0201]  45.54 147.28 180 bottom
CG203  0.47u/6.3V_2  [C0201]  60.18 147.17 180 bottom
CG204  0.47u/6.3V_2  [C0201]  59.18 147.16 0 bottom
CG205  10u/6.3V_6  [C0603]  77.81 147.03 90 bottom
CG206  0.47u/6.3V_2  [C0201]  33.39 147.01 0 bottom
CG207  0.47u/6.3V_2  [C0201]  57.11 147 270 bottom
CG208  0.47u/6.3V_2  [C0201]  49.34 147 0 bottom
CG209  0.47u/6.3V_2  [C0201]  44.16 146.99 270 bottom
CG210  0.47u/6.3V_2  [C0201]  41.91 146.97 270 bottom
CG211  0.47u/6.3V_2  [C0201]  74.54 146.97 270 bottom
CG212  0.47u/6.3V_2  [C0201]  26.45 146.96 0 bottom
CG213  0.47u/6.3V_2  [C0201]  58.19 146.95 180 bottom
CG214  0.47u/6.3V_2  [C0201]  27.63 146.95 180 bottom
CG215  0.47u/6.3V_2  [C0201]  28.62 146.93 0 bottom
CG216  0.47u/6.3V_2  [C0201]  46.9 146.65 270 bottom
CG217  0.47u/6.3V_2  [C0201]  40.48 146.59 0 bottom
CG218  22u/6.3V_6  [C0603]  86.9 146.59 180 bottom
CG219  0.47u/6.3V_2  [C0201]  83.84 146.24 180 bottom
CG220  0.47u/6.3V_2  [C0201]  34 146.24 0 bottom
CG221  22u/6.3V_6  [C0603]  39.01 146.17 270 bottom
CG222  0.47u/6.3V_2  [C0201]  68.61 146.14 180 bottom
CG223  0.47u/6.3V_2  [C0201]  60.23 146.07 180 bottom
CG224  0.47u/6.3V_2  [C0201]  71.66 146.04 0 bottom
CG225  0.47u/6.3V_2  [C0201]  37.76 145.87 270 bottom
CG226  22u/6.3V_6  [C0603]  54.21 145.67 270 bottom
CG227  0.47u/6.3V_2  [C0201]  41.9 145.56 0 bottom
CG228  0.47u/6.3V_2  [C0201]  68.6 145.4 180 bottom
CG229  0.47u/6.3V_2  [C0201]  76.93 145.35 180 bottom
CG230  0.47u/6.3V_2  [C0201]  83.6 145.3 90 bottom
CG231  22u/6.3V_6  [C0603]  31.75 145.29 180 bottom
CG232  0.47u/6.3V_2  [C0201]  56.5 145.21 90 bottom
CG233  0.47u/6.3V_2  [C0201]  52.98 145.2 90 bottom
CG234  0.47u/6.3V_2  [C0201]  78.68 145.18 270 bottom
CG235  10u/6.3V_6  [C0603]  62.78 145.15 90 bottom
CG236  0.47u/6.3V_2  [C0201]  25.88 144.83 0 bottom
CG237  0.47u/6.3V_2  [C0201]  79.66 144.76 180 bottom
CG238  22u/6.3V_6  [C0603]  46.73 144.72 270 bottom
CG239  0.47u/6.3V_2  [C0201]  71.85 144.52 270 bottom
CG240  0.47u/6.3V_2  [C0201]  40.93 144.41 0 bottom
CG241  0.47u/6.3V_2  [C0201]  64.01 144.27 180 bottom
CG242  0.47u/6.3V_2  [C0201]  68.5 144.26 180 bottom
CG243  0.47u/6.3V_2  [C0201]  83.78 144.24 180 bottom
CG244  0.47u/6.3V_2  [C0201]  37.79 144.24 270 bottom
CG245  0.47u/6.3V_2  [C0201]  25.78 144.09 0 bottom
CG246  0.47u/6.3V_2  [C0201]  45.41 144.09 90 bottom
CG247  0.47u/6.3V_2  [C0201]  31.36 144.08 180 bottom
CG248  0.47u/6.3V_2  [C0201]  47.82 144.01 270 bottom
CG249  0.47u/6.3V_2  [C0201]  52.98 143.93 90 bottom
CG250  0.47u/6.3V_2  [C0201]  32.49 143.69 90 bottom
CG251  0.47u/6.3V_2  [C0201]  56.5 143.69 90 bottom
CG252  0.47u/6.3V_2  [C0201]  55.51 143.69 90 bottom
CG253  *10u/6.3V_6  [C0603]  77.36 143.66 90 bottom
CG254  0.47u/6.3V_2  [C0201]  68.52 143.53 180 bottom
CG255  0.47u/6.3V_2  [C0201]  71.85 143.42 90 bottom
CG256  0.47u/6.3V_2  [C0201]  40.94 143.42 0 bottom
CG257  0.47u/6.3V_2  [C0201]  63.18 143.29 90 bottom
CG258  0.47u/6.3V_2  [C0201]  48.84 143.28 90 bottom
CG259  0.47u/6.3V_2  [C0201]  25.99 143.18 270 bottom
CG260  0.47u/6.3V_2  [C0201]  37.92 143.09 180 bottom
CG261  0.47u/6.3V_2  [C0201]  83.72 143.03 180 bottom
CG262  0.47u/6.3V_2  [C0201]  61.74 143.01 0 bottom
CG263  0.47u/6.3V_2  [C0201]  68.55 142.53 180 bottom
CG264  0.47u/6.3V_2  [C0201]  52.98 142.32 90 bottom
CG265  22u/6.3V_6  [C0603]  31.34 142.26 270 bottom
CG266  0.47u/6.3V_2  [C0201]  61.73 142.23 0 bottom
CG267  0.47u/6.3V_2  [C0201]  38.01 142.11 180 bottom
CG268  22u/6.3V_6  [C0603]  46.88 142.08 270 bottom
CG269  0.47u/6.3V_2  [C0201]  72.48 141.98 0 bottom
CG270  0.47u/6.3V_2  [C0201]  41.78 141.88 0 bottom
CG271  22u/6.3V_6  [C0603]  54.75 141.86 270 bottom
CG272  22u/6.3V_6  [C0603]  56.2 141.85 270 bottom
CG273  0.47u/6.3V_2  [C0201]  64.23 141.84 0 bottom
CG274  0.47u/6.3V_2  [C0201]  57.98 141.68 90 bottom
CG275  0.47u/6.3V_2  [C0201]  33.65 141.49 0 bottom
CG276  0.47u/6.3V_2  [C0201]  52.03 141.2 180 bottom
CG277  0.47u/6.3V_2  [C0201]  60.52 141.17 180 bottom
CG278  0.47u/6.3V_2  [C0201]  81.37 141.16 0 bottom
CG279  0.47u/6.3V_2  [C0201]  76.01 141.09 180 bottom
CG280  0.47u/6.3V_2  [C0201]  45.21 141.06 180 bottom
CG281  22u/6.3V_6  [C0603]  37.03 141.01 0 bottom
CG282  0.47u/6.3V_2  [C0201]  29.97 141.01 180 bottom
CG283  10u/6.3V_6  [C0603]  67.82 140.95 0 bottom
CG284  22u/6.3V_6  [C0603]  65.04 140.74 180 bottom
CG285  22u/6.3V_6  [C0603]  42.64 140.71 180 bottom
CG286  4.7u/6.3V_6  [C0603]  79.5 140.66 180 bottom
CG287  10u/6.3V_6  [C0603]  34.33 140.4 180 bottom
CG288  4.7u/6.3V_6  [C0603]  49.19 140.33 180 bottom
CG289  22u/6.3V_6  [C0603]  74.03 140.32 270 bottom
CG290  22u/6.3V_6  [C0603]  59.32 140.23 270 bottom
CG291  22u/6.3V_6  [C0603]  52.34 140.05 0 bottom
CG292  47u/6.3V_8  [C0805]  42.69 138.85 180 bottom
CG293  22u/6.3V_6  [C0603]  34.31 138.85 180 bottom
CG294  10u/6.3V_6  [C0603]  10.81 135.78 180 bottom
CG295  0.47u/6.3V_2  [C0201]  12.33 134.32 0 bottom
CG296  0.47u/6.3V_2  [C0201]  11 134.32 0 bottom
CG297  0.47u/6.3V_2  [C0201]  9.9 133.24 270 bottom
CG298  22u/6.3V_6  [C0603]  8.29 132.06 270 bottom
CG299  0.47u/6.3V_2  [C0201]  18.81 130.91 180 bottom
CG300  0.47u/6.3V_2  [C0201]  15.77 130.78 0 bottom
CG301  0.47u/6.3V_2  [C0201]  9.9 130.52 90 bottom
CG302  0.47u/6.3V_2  [C0201]  8.88 130.37 0 bottom
CG303  0.47u/6.3V_2  [C0201]  12.05 130.17 0 bottom
CG304  0.47u/6.3V_2  [C0201]  14.29 130.06 180 bottom
CG305  *47u/6.3V_8  [C0805]  93.85 129.97 180 bottom
CG306  10u/6.3V_6  [C0603]  96.29 129.41 270 bottom
CG307  0.47u/6.3V_2  [C0201]  11.64 129.41 0 bottom
CG308  0.47u/6.3V_2  [C0201]  53.33 129.36 180 bottom
CG309  47u/6.3V_8  [C0805]  100.54 129.25 0 bottom
CG310  0.47u/6.3V_2  [C0201]  89.48 129.12 180 bottom
CG311  22u/6.3V_6  [C0603]  13.76 128.72 0 bottom
CG312  *47u/6.3V_8  [C0805]  61.87 128.64 180 bottom
CG313  4.7u/6.3V_6  [C0603]  9.75 128.64 0 bottom
CG314  22u/6.3V_6  [C0603]  17.72 128.52 0 bottom
CG315  10u/6.3V_6  [C0603]  45.93 128.86 0 bottom
CG316  0.47u/6.3V_2  [C0201]  22.01 128.44 180 bottom
CG317  0.47u/6.3V_2  [C0201]  46.19 127.79 180 bottom
CG318  0.47u/6.3V_2  [C0201]  64.05 128.15 0 bottom
CG319  0.47u/6.3V_2  [C0201]  89.73 127.75 180 bottom
CG320  0.47u/6.3V_2  [C0201]  88.36 127.73 180 bottom
CG321  0.47u/6.3V_2  [C0201]  93.56 127.67 180 bottom
CG322  0.47u/6.3V_2  [C0201]  87.12 127.65 180 bottom
CG323  0.47u/6.3V_2  [C0201]  98.15 127.65 0 bottom
CG324  0.47u/6.3V_2  [C0201]  96.68 127.64 0 bottom
CG325  0.47u/6.3V_2  [C0201]  22.84 127.63 180 bottom
CG326  0.47u/6.3V_2  [C0201]  95.21 127.6 180 bottom
CG327  0.47u/6.3V_2  [C0201]  12.3 127.59 0 bottom
CG328  0.47u/6.3V_2  [C0201]  21.81 127.59 0 bottom
CG329  0.47u/6.3V_2  [C0201]  13.4 127.17 270 bottom
CG330  0.47u/6.3V_2  [C0201]  11.98 126.84 0 bottom
CG331  0.47u/6.3V_2  [C0201]  10.07 126.79 270 bottom
CG332  22u/6.3V_6  [C0603]  101.16 126.79 90 bottom
CG333  0.47u/6.3V_2  [C0201]  90.88 126.76 180 bottom
CG334  0.47u/6.3V_2  [C0201]  99.72 126.54 270 bottom
CG335  10u/6.3V_6  [C0603]  8.51 126.46 270 bottom
CG336  0.47u/6.3V_2  [C0201]  24.63 126.35 270 bottom
CG337  0.47u/6.3V_2  [C0201]  19.5 126.19 270 bottom
CG338  0.47u/6.3V_2  [C0201]  14.87 126.19 270 bottom
CG339  0.47u/6.3V_2  [C0201]  85.03 125.95 90 bottom
CG340  0.47u/6.3V_2  [C0201]  25.37 125.72 270 bottom
CG341  0.47u/6.3V_2  [C0201]  90.97 125.46 270 bottom
CG342  0.47u/6.3V_2  [C0201]  18 125.02 90 bottom
CG343  0.47u/6.3V_2  [C0201]  9.62 124.99 270 bottom
CG344  0.47u/6.3V_2  [C0201]  37.37 124.43 0 bottom
CG345  10u/6.3V_6  [C0603]  101.16 124.15 270 bottom
CG346  0.47u/6.3V_2  [C0201]  94.7 124.12 90 bottom
CG347  0.47u/6.3V_2  [C0201]  90.11 124.07 90 bottom
CG348  0.47u/6.3V_2  [C0201]  99.7 123.91 90 bottom
CG349  0.47u/6.3V_2  [C0201]  18.21 123.85 270 bottom
CG350  10u/6.3V_6  [C0603]  83.84 123.84 270 bottom
CG351  0.47u/6.3V_2  [C0201]  43.52 123.84 180 bottom
CG352  22u/6.3V_6  [C0603]  24.97 123.79 270 bottom
CG353  0.47u/6.3V_2  [C0201]  85.01 123.69 90 bottom
CG354  0.47u/6.3V_2  [C0201]  9.75 123.59 90 bottom
CG355  0.47u/6.3V_2  [C0201]  96 123.52 0 bottom
CG356  0.47u/6.3V_2  [C0201]  63.31 123.4 90 bottom
CG357  0.47u/6.3V_2  [C0201]  23.45 123.37 180 bottom
CG358  10u/6.3V_6  [C0603]  8.52 123.23 90 bottom
CG359  0.47u/6.3V_2  [C0201]  20.21 123.19 180 bottom
CG360  0.47u/6.3V_2  [C0201]  50.28 123.11 0 bottom
CG361  0.47u/6.3V_2  [C0201]  54.8 123.07 0 bottom
CG362  0.47u/6.3V_2  [C0201]  62.44 123.04 180 bottom
CG363  0.47u/6.3V_2  [C0201]  18.83 122.97 0 bottom
CG364  0.47u/6.3V_2  [C0201]  49.05 122.86 270 bottom
CG365  0.47u/6.3V_2  [C0201]  45.67 122.85 0 bottom
CG366  0.47u/6.3V_2  [C0201]  86.77 122.69 0 bottom
CG367  0.47u/6.3V_2  [C0201]  9.74 122.66 180 bottom
CG368  0.47u/6.3V_2  [C0201]  13.96 122.58 0 bottom
CG369  0.47u/6.3V_2  [C0201]  12.35 122.57 0 bottom
CG370  0.47u/6.3V_2  [C0201]  10.75 122.57 0 bottom
CG371  0.47u/6.3V_2  [C0201]  98.76 122.57 0 bottom
CG372  0.47u/6.3V_2  [C0201]  47.85 122.57 0 bottom
CG373  0.47u/6.3V_2  [C0201]  22.18 122.53 180 bottom
CG374  0.47u/6.3V_2  [C0201]  46.86 122.43 0 bottom
CG375  0.47u/6.3V_2  [C0201]  51.84 122.41 270 bottom
CG376  0.47u/6.3V_2  [C0201]  20.24 122.4 180 bottom
CG377  0.47u/6.3V_2  [C0201]  56.37 122.4 270 bottom
CG378  0.47u/6.3V_2  [C0201]  57.61 122.4 0 bottom
CG379  10u/6.3V_6  [C0603]  88.66 122.37 0 bottom
CG380  22u/6.3V_6  [C0603]  61.24 122.3 90 bottom
CG381  0.47u/6.3V_2  [C0201]  60.17 122.23 270 bottom
CG382  0.47u/6.3V_2  [C0201]  62.58 122.17 90 bottom
CG383  0.47u/6.3V_2  [C0201]  100.3 122.16 90 bottom
CG384  10u/6.3V_6  [C0603]  96.87 122.11 180 bottom
CG385  0.47u/6.3V_2  [C0201]  47.85 121.85 0 bottom
CG386  10u/6.3V_6  [C0603]  44.13 121.85 135 bottom
CG387  *47u/6.3V_8  [C0805]  49.82 128.73 0 bottom
CG388  0.47u/6.3V_2  [C0201]  13.98 121.78 0 bottom
CG389  22u/6.3V_6  [C0603]  58.98 121.72 90 bottom
CG390  0.47u/6.3V_2  [C0201]  57.6 121.68 180 bottom
CG391  0.47u/6.3V_2  [C0201]  49.55 121.49 90 bottom
CG392  0.47u/6.3V_2  [C0201]  48.82 121.48 90 bottom
CG393  10u/6.3V_6  [C0603]  50.62 121.44 90 bottom
CG394  22u/6.3V_6  [C0603]  52.9 121.43 90 bottom
CG395  0.47u/6.3V_2  [C0201]  56.38 121.42 90 bottom
CG396  22u/6.3V_6  [C0603]  55.3 121.4 90 bottom
CG397  0.47u/6.3V_2  [C0201]  54.1 121.3 0 bottom
CG398  10u/6.3V_6  [C0603]  20.82 121.28 0 bottom
CG399  0.47u/6.3V_2  [C0201]  60.17 121.24 90 bottom
CG400  0.47u/6.3V_2  [C0201]  51.84 121.2 90 bottom
CG401  0.47u/6.3V_2  [C0201]  87.79 121.15 0 bottom
CG402  10u/6.3V_6  [C0603]  37.99 121.07 180 bottom
CG403  22u/6.3V_6  [C0603]  11.04 121.07 180 bottom
CG404  0.47u/6.3V_2  [C0201]  97.9 120.89 180 bottom
CG405  0.47u/6.3V_2  [C0201]  43.21 120.83 90 bottom
CG406  0.47u/6.3V_2  [C0201]  57.83 120.8 270 bottom
CG407  0.47u/6.3V_2  [C0201]  62.39 120.76 270 bottom
CG408  10u/6.3V_6  [C0603]  46.32 120.73 90 bottom
CG409  0.47u/6.3V_2  [C0201]  47.39 120.73 90 bottom
CG410  0.47u/6.3V_2  [C0201]  48.1 120.72 270 bottom
CG411  0.47u/6.3V_2  [C0201]  61.26 120.62 180 bottom
CG412  0.47u/6.3V_2  [C0201]  49.25 120.62 0 bottom
CG413  0.47u/6.3V_2  [C0201]  54.1 120.57 0 bottom
CG414  0.47u/6.3V_2  [C0201]  56.83 120.56 180 bottom
CG415  0.47u/6.3V_2  [C0201]  100.05 120.42 0 bottom
CG416  0.47u/6.3V_2  [C0201]  90.95 120.41 270 bottom
CG417  0.47u/6.3V_2  [C0201]  96.16 120.33 270 bottom
CG418  0.47u/6.3V_2  [C0201]  64.71 120.33 90 bottom
CG419  0.47u/6.3V_2  [C0201]  63.28 120.32 270 bottom
CG420  0.47u/6.3V_2  [C0201]  64 120.32 270 bottom
CG421  1u/6.3V_2  [C0201]  85.64 120.13 90 bottom
CG422  10u/6.3V_6  [C0603]  8.2 120.11 270 bottom
CG423  22u/6.3V_6  [C0603]  84.52 119.94 90 bottom
CG424  0.47u/6.3V_2  [C0201]  62.39 119.89 0 bottom
CG425  0.47u/6.3V_2  [C0201]  90.24 119.88 270 bottom
CG426  0.47u/6.3V_2  [C0201]  13.86 119.77 0 bottom
CG427  0.47u/6.3V_2  [C0201]  22.86 119.76 180 bottom
CG428  0.47u/6.3V_2  [C0201]  20.1 119.75 180 bottom
CG429  0.47u/6.3V_2  [C0201]  21.25 119.73 180 bottom
CG430  0.47u/6.3V_2  [C0201]  10.65 119.71 0 bottom
CG431  0.47u/6.3V_2  [C0201]  12.23 119.7 0 bottom
CG432  10u/6.3V_6  [C0603]  101.4 119.62 90 bottom
CG433  0.47u/6.3V_2  [C0201]  94.59 119.56 180 bottom
CG434  10u/6.3V_6  [C0603]  44.3 119.55 180 bottom
CG435  0.47u/6.3V_2  [C0201]  49.68 119.49 90 bottom
CG436  0.47u/6.3V_2  [C0201]  48.97 119.49 270 bottom
CG437  0.47u/6.3V_2  [C0201]  48.25 119.49 270 bottom
CG438  0.47u/6.3V_2  [C0201]  47.54 119.49 270 bottom
CG439  0.47u/6.3V_2  [C0201]  54.66 119.37 90 bottom
CG440  0.47u/6.3V_2  [C0201]  53.95 119.37 270 bottom
CG441  0.47u/6.3V_2  [C0201]  53.24 119.37 270 bottom
CG442  0.47u/6.3V_2  [C0201]  52.53 119.37 90 bottom
CG443  0.47u/6.3V_2  [C0201]  51.82 119.37 270 bottom
CG444  0.47u/6.3V_2  [C0201]  55.37 119.37 270 bottom
CG445  0.47u/6.3V_2  [C0201]  51.1 119.37 90 bottom
CG446  0.47u/6.3V_2  [C0201]  50.39 119.37 90 bottom
CG447  0.47u/6.3V_2  [C0201]  57.88 119.33 90 bottom
CG448  0.47u/6.3V_2  [C0201]  58.6 119.33 270 bottom
CG449  0.47u/6.3V_2  [C0201]  59.31 119.33 270 bottom
CG450  0.47u/6.3V_2  [C0201]  60.02 119.33 90 bottom
CG451  0.47u/6.3V_2  [C0201]  57.17 119.33 270 bottom
CG452  0.47u/6.3V_2  [C0201]  60.73 119.33 270 bottom
CG453  0.47u/6.3V_2  [C0201]  56.46 119.33 90 bottom
CG454  0.47u/6.3V_2  [C0201]  61.45 119.33 90 bottom
CG455  10u/6.3V_6  [C0603]  26 119.05 90 bottom
CG456  0.47u/6.3V_2  [C0201]  63.8 118.9 0 bottom
CG457  0.47u/6.3V_2  [C0201]  62.42 118.88 180 bottom
CG458  0.47u/6.3V_2  [C0201]  24.74 118.86 270 bottom
CG459  0.47u/6.3V_2  [C0201]  37.42 118.5 90 bottom
CG460  0.47u/6.3V_2  [C0201]  43.56 118.48 0 bottom
CG461  0.47u/6.3V_2  [C0201]  45.1 118.31 180 bottom
CG462  0.47u/6.3V_2  [C0201]  84.6 118.1 0 bottom
CG463  0.47u/6.3V_2  [C0201]  91.51 118.05 90 bottom
CG464  0.47u/6.3V_2  [C0201]  64.51 118.03 270 bottom
CG465  0.47u/6.3V_2  [C0201]  61.38 118.03 270 bottom
CG466  0.47u/6.3V_2  [C0201]  60.66 118.02 90 bottom
CG467  0.47u/6.3V_2  [C0201]  59.24 118.02 90 bottom
CG468  0.47u/6.3V_2  [C0201]  62.09 118.02 90 bottom
CG469  0.47u/6.3V_2  [C0201]  59.95 118.02 270 bottom
CG470  0.47u/6.3V_2  [C0201]  58.52 118.02 90 bottom
CG471  0.47u/6.3V_2  [C0201]  57.81 118.02 270 bottom
CG472  0.47u/6.3V_2  [C0201]  57.1 118.02 90 bottom
CG473  0.47u/6.3V_2  [C0201]  56.38 118.02 270 bottom
CG474  0.47u/6.3V_2  [C0201]  55.67 118.02 90 bottom
CG475  0.47u/6.3V_2  [C0201]  63.79 118.01 90 bottom
CG476  0.47u/6.3V_2  [C0201]  50.8 118 90 bottom
CG477  0.47u/6.3V_2  [C0201]  50.08 118 270 bottom
CG478  0.47u/6.3V_2  [C0201]  9.75 117.9 0 bottom
CG479  0.47u/6.3V_2  [C0201]  62.94 117.89 180 bottom
CG480  0.47u/6.3V_2  [C0201]  43.57 117.75 0 bottom
CG481  0.47u/6.3V_2  [C0201]  45.11 117.57 180 bottom
CG482  47u/6.3V_8  [C0805]  46.75 117.39 90 bottom
CG483  10u/6.3V_6  [C0603]  8.2 117.21 270 bottom
CG484  22u/6.3V_6  [C0603]  37.53 117.19 180 bottom
CG485  0.47u/6.3V_2  [C0201]  99.73 117.16 90 bottom
CG486  47u/6.3V_8  [C0805]  53.84 116.97 270 bottom
CG487  10u/6.3V_6  [C0603]  25.67 116.83 0 bottom
CG488  0.47u/6.3V_2  [C0201]  65.44 116.81 90 bottom
CG489  0.47u/6.3V_2  [C0201]  64.72 116.76 90 bottom
CG490  0.47u/6.3V_2  [C0201]  9.52 116.75 0 bottom
CG491  0.47u/6.3V_2  [C0201]  63.29 116.64 270 bottom
CG492  0.47u/6.3V_2  [C0201]  62.58 116.64 270 bottom
CG493  0.47u/6.3V_2  [C0201]  61.87 116.64 270 bottom
CG494  0.47u/6.3V_2  [C0201]  61.15 116.64 90 bottom
CG495  0.47u/6.3V_2  [C0201]  64.01 116.64 270 bottom
CG496  0.47u/6.3V_2  [C0201]  60.44 116.64 270 bottom
CG497  10u/6.3V_6  [C0603]  58.77 116.6 180 bottom
CG498  0.47u/6.3V_2  [C0201]  50.75 116.6 270 bottom
CG499  0.47u/6.3V_2  [C0201]  50.03 116.6 90 bottom
CG500  0.47u/6.3V_2  [C0201]  57.1 116.6 270 bottom
CG501  0.47u/6.3V_2  [C0201]  56.39 116.6 90 bottom
CG502  0.47u/6.3V_2  [C0201]  55.68 116.6 90 bottom
CG503  0.47u/6.3V_2  [C0201]  43.55 116.56 0 bottom
CG504  0.47u/6.3V_2  [C0201]  45.02 116.56 0 bottom
CG505  0.47u/6.3V_2  [C0201]  21.69 116.3 180 bottom
CG506  0.47u/6.3V_2  [C0201]  15.03 116.17 0 bottom
CG507  0.47u/6.3V_2  [C0201]  19.55 116.16 180 bottom
CG508  0.47u/6.3V_2  [C0201]  86.3 116 0 bottom
CG509  0.47u/6.3V_2  [C0201]  87.61 115.97 0 bottom
CG510  0.47u/6.3V_2  [C0201]  95.79 115.94 180 bottom
CG511  0.47u/6.3V_2  [C0201]  97.2 115.94 180 bottom
CG512  0.47u/6.3V_2  [C0201]  94.34 115.93 0 bottom
CG513  0.47u/6.3V_2  [C0201]  98.77 115.92 180 bottom
CG514  0.47u/6.3V_2  [C0201]  90.29 115.91 180 bottom
CG515  0.47u/6.3V_2  [C0201]  89.15 115.91 0 bottom
CG516  0.47u/6.3V_2  [C0201]  9.95 115.87 90 bottom
CG517  0.47u/6.3V_2  [C0201]  71.78 115.78 270 bottom
CG518  0.47u/6.3V_2  [C0201]  64.07 115.72 180 bottom
CG519  0.47u/6.3V_2  [C0201]  65.06 115.69 0 bottom
CG520  0.47u/6.3V_2  [C0201]  66.05 115.69 180 bottom
CG521  0.47u/6.3V_2  [C0201]  23.85 115.61 90 bottom
CG522  10u/6.3V_6  [C0603]  44.28 115.5 180 bottom
CG523  0.47u/6.3V_2  [C0201]  18.7 115.39 180 bottom
CG524  0.47u/6.3V_2  [C0201]  63.08 115.37 0 bottom
CG525  0.47u/6.3V_2  [C0201]  50.83 115.2 90 bottom
CG526  0.47u/6.3V_2  [C0201]  50.1 115.2 270 bottom
CG527  22u/6.3V_6  [C0603]  56.55 115.18 0 bottom
CG528  0.47u/6.3V_2  [C0201]  58.93 115.16 270 bottom
CG529  0.47u/6.3V_2  [C0201]  58.22 115.16 90 bottom
CG530  0.47u/6.3V_2  [C0201]  61.79 115.16 270 bottom
CG531  0.47u/6.3V_2  [C0201]  59.64 115.16 270 bottom
CG532  0.47u/6.3V_2  [C0201]  60.36 115.16 90 bottom
CG533  0.47u/6.3V_2  [C0201]  61.07 115.15 270 bottom
CG534  0.47u/6.3V_2  [C0201]  90.12 115.08 180 bottom
CG535  22u/6.3V_6  [C0603]  37.74 115.08 180 bottom
CG536  0.47u/6.3V_2  [C0201]  64.07 115.01 180 bottom
CG537  0.47u/6.3V_2  [C0201]  13.58 114.88 0 bottom
CG538  22u/6.3V_6  [C0603]  96.03 114.85 0 bottom
CG539  22u/6.3V_6  [C0603]  87.12 114.78 180 bottom
CG540  0.47u/6.3V_2  [C0201]  11.73 114.72 0 bottom
CG541  0.47u/6.3V_2  [C0201]  65.06 114.7 0 bottom
CG542  0.47u/6.3V_2  [C0201]  66.04 114.7 180 bottom
CG543  10u/6.3V_6  [C0603]  24.97 114.69 270 bottom
CG544  0.47u/6.3V_2  [C0201]  22.44 114.57 180 bottom
CG545  0.47u/6.3V_2  [C0201]  63.22 114.48 270 bottom
CG546  0.47u/6.3V_2  [C0201]  62.51 114.47 90 bottom
CG547  0.47u/6.3V_2  [C0201]  44.97 114.43 180 bottom
CG548  0.47u/6.3V_2  [C0201]  43.83 114.43 0 bottom
CG549  0.47u/6.3V_2  [C0201]  91.23 114.37 0 bottom
CG550  0.47u/6.3V_2  [C0201]  64.07 114.3 0 bottom
CG551  0.47u/6.3V_2  [C0201]  58.98 114.28 0 bottom
CG552  0.47u/6.3V_2  [C0201]  61.11 114.27 0 bottom
CG553  22u/6.3V_6  [C0603]  93.03 114.11 180 bottom
CG554  47u/6.3V_8  [C0805]  46.75 114.05 270 bottom
CG555  4.7u/6.3V_6  [C0603]  9.87 114.02 0 bottom
CG556  0.47u/6.3V_2  [C0201]  50.83 113.8 270 bottom
CG557  0.47u/6.3V_2  [C0201]  50.1 113.8 90 bottom
CG558  0.47u/6.3V_2  [C0201]  57.07 113.79 90 bottom
CG559  0.47u/6.3V_2  [C0201]  56.34 113.79 90 bottom
CG560  0.47u/6.3V_2  [C0201]  55.6 113.79 270 bottom
CG561  22u/6.3V_6  [C0603]  53.81 113.77 90 bottom
CG562  10u/6.3V_6  [C0603]  52.05 113.77 90 bottom
CG563  0.47u/6.3V_2  [C0201]  66.15 113.69 180 bottom
CG564  10u/6.3V_6  [C0603]  98.7 113.66 0 bottom
CG565  22u/6.3V_6  [C0603]  15.28 113.58 180 bottom
CG566  0.47u/6.3V_2  [C0201]  65.16 113.54 0 bottom
CG567  10u/6.3V_6  [C0603]  44.34 113.37 180 bottom
CG568  0.47u/6.3V_2  [C0201]  11.86 113.12 0 bottom
CG569  0.47u/6.3V_2  [C0201]  61.22 113.05 90 bottom
